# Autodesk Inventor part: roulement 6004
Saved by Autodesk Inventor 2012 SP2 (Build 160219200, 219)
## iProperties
Created: 2013-04
Part Number: roulement 6004
Material: Default
Document SubType Name: Modeling
Designer: papa
Density: 1 g/cm^3
Mass: 8.2699 g
Surface Area: 78.9198 cm^2
Volume: 8.2699 cm^3
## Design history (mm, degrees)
node "roulement 60041"
node "roulement 6004"
node "roulement 6004_1"
node "roulement 6004_2"
node "roulement 6004_3"
node "roulement 6004_4"
node "roulement 6004_5"
node "roulement 6004_6"
node "roulement 6004_7"
node "roulement 6004_8"
node "Base1"
node "Base2"
node "Base3"
node "Base4"
node "Base5"
node "Base6"
node "Base7"
node "Base8"
node "Base9"
